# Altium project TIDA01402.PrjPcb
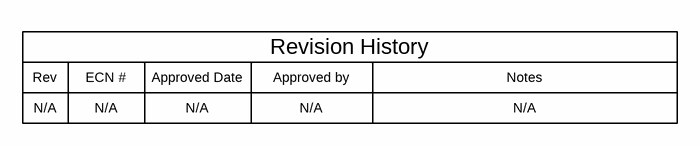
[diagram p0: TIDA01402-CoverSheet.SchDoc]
CopyrightYear: 2017; PCB_Layout: Errol Leon; PCB_Rev: E1; PRJ_Customer: Public Release; PRJ_Engineer: Errol Leon; PRJ_Number: TIDA01042; PRJ_Title: Minimizing DAC INL with zero-crossover op amp; SCH_Rev: E1; TechSupport: http://www.ti.com/support; TID: TIDA01042
3 sheets, 50 parts. Net scope: global (net labels, ports and power ports of the same name join across sheets).
Board file: TIDA01402.PcbDoc
Sheets:
  TIDA01402-CoverSheet.SchDoc
  TIDA01402-Schematic.SchDoc
  TIDA01402-Hardware.SchDoc

## Sheet TIDA01402-CoverSheet.SchDoc
size 431 x 279 mm; Date: Not shown in title block; ApprovedBy: Not shown in title block; CheckedBy: Not shown in title block; Author: Not shown in title block; CompanyName: Not shown in title block; Engineer: Not shown in title block; Organization: Not shown in title block; Address1: Not shown in title block; Address2: Not shown in title block; Address3: Not shown in title block; Address4: Not shown in title block; DocumentNumber: 1; Revision: Use project parameter SCH_Rev; SheetNumber: 1; SheetTotal: 3; PageSetup: Record=PageOptions¦CenterHorizontal=True¦CenterVertical=True¦PrintScale=1.00¦XCorrection=1.00¦YCorrection=1.00¦PrintKind=0¦BorderSize=5000000¦LeftOffset=0¦BottomOffset=0¦Orientation=2¦PaperLength=1000¦PaperWidth=1000¦Scale=100¦PaperSource=15¦PrintQuality=600¦MediaType=1¦DitherType=10¦PaperKind=Letter¦PrintScaleMode=1

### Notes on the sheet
- Rev
- N/A
- ECN #
- Approved Date
- Approved by
- Revision History
- Notes

## Sheet TIDA01402-Schematic.SchDoc
size 431 x 279 mm; Date: Not shown in title block; ApprovedBy: Not shown in title block; CheckedBy: Not shown in title block; Author: Not shown in title block; CompanyName: Not shown in title block; Engineer: Not shown in title block; Organization: Not shown in title block; Address1: Not shown in title block; Address2: Not shown in title block; Address3: Not shown in title block; Address4: Not shown in title block; DocumentNumber: 1; Revision: Use project parameter SCH_Rev; SheetNumber: 2; SheetTotal: 3; PageSetup: Record=PageOptions¦CenterHorizontal=True¦CenterVertical=True¦PrintScale=1.00¦XCorrection=1.00¦YCorrection=1.00¦PrintKind=0¦BorderSize=5000000¦LeftOffset=0¦BottomOffset=0¦Orientation=2¦PaperLength=1000¦PaperWidth=1000¦Scale=100¦PaperSource=15¦PrintQuality=-3¦MediaType=1¦DitherType=10¦PrintScaleMode=1¦PaperKind=Letter
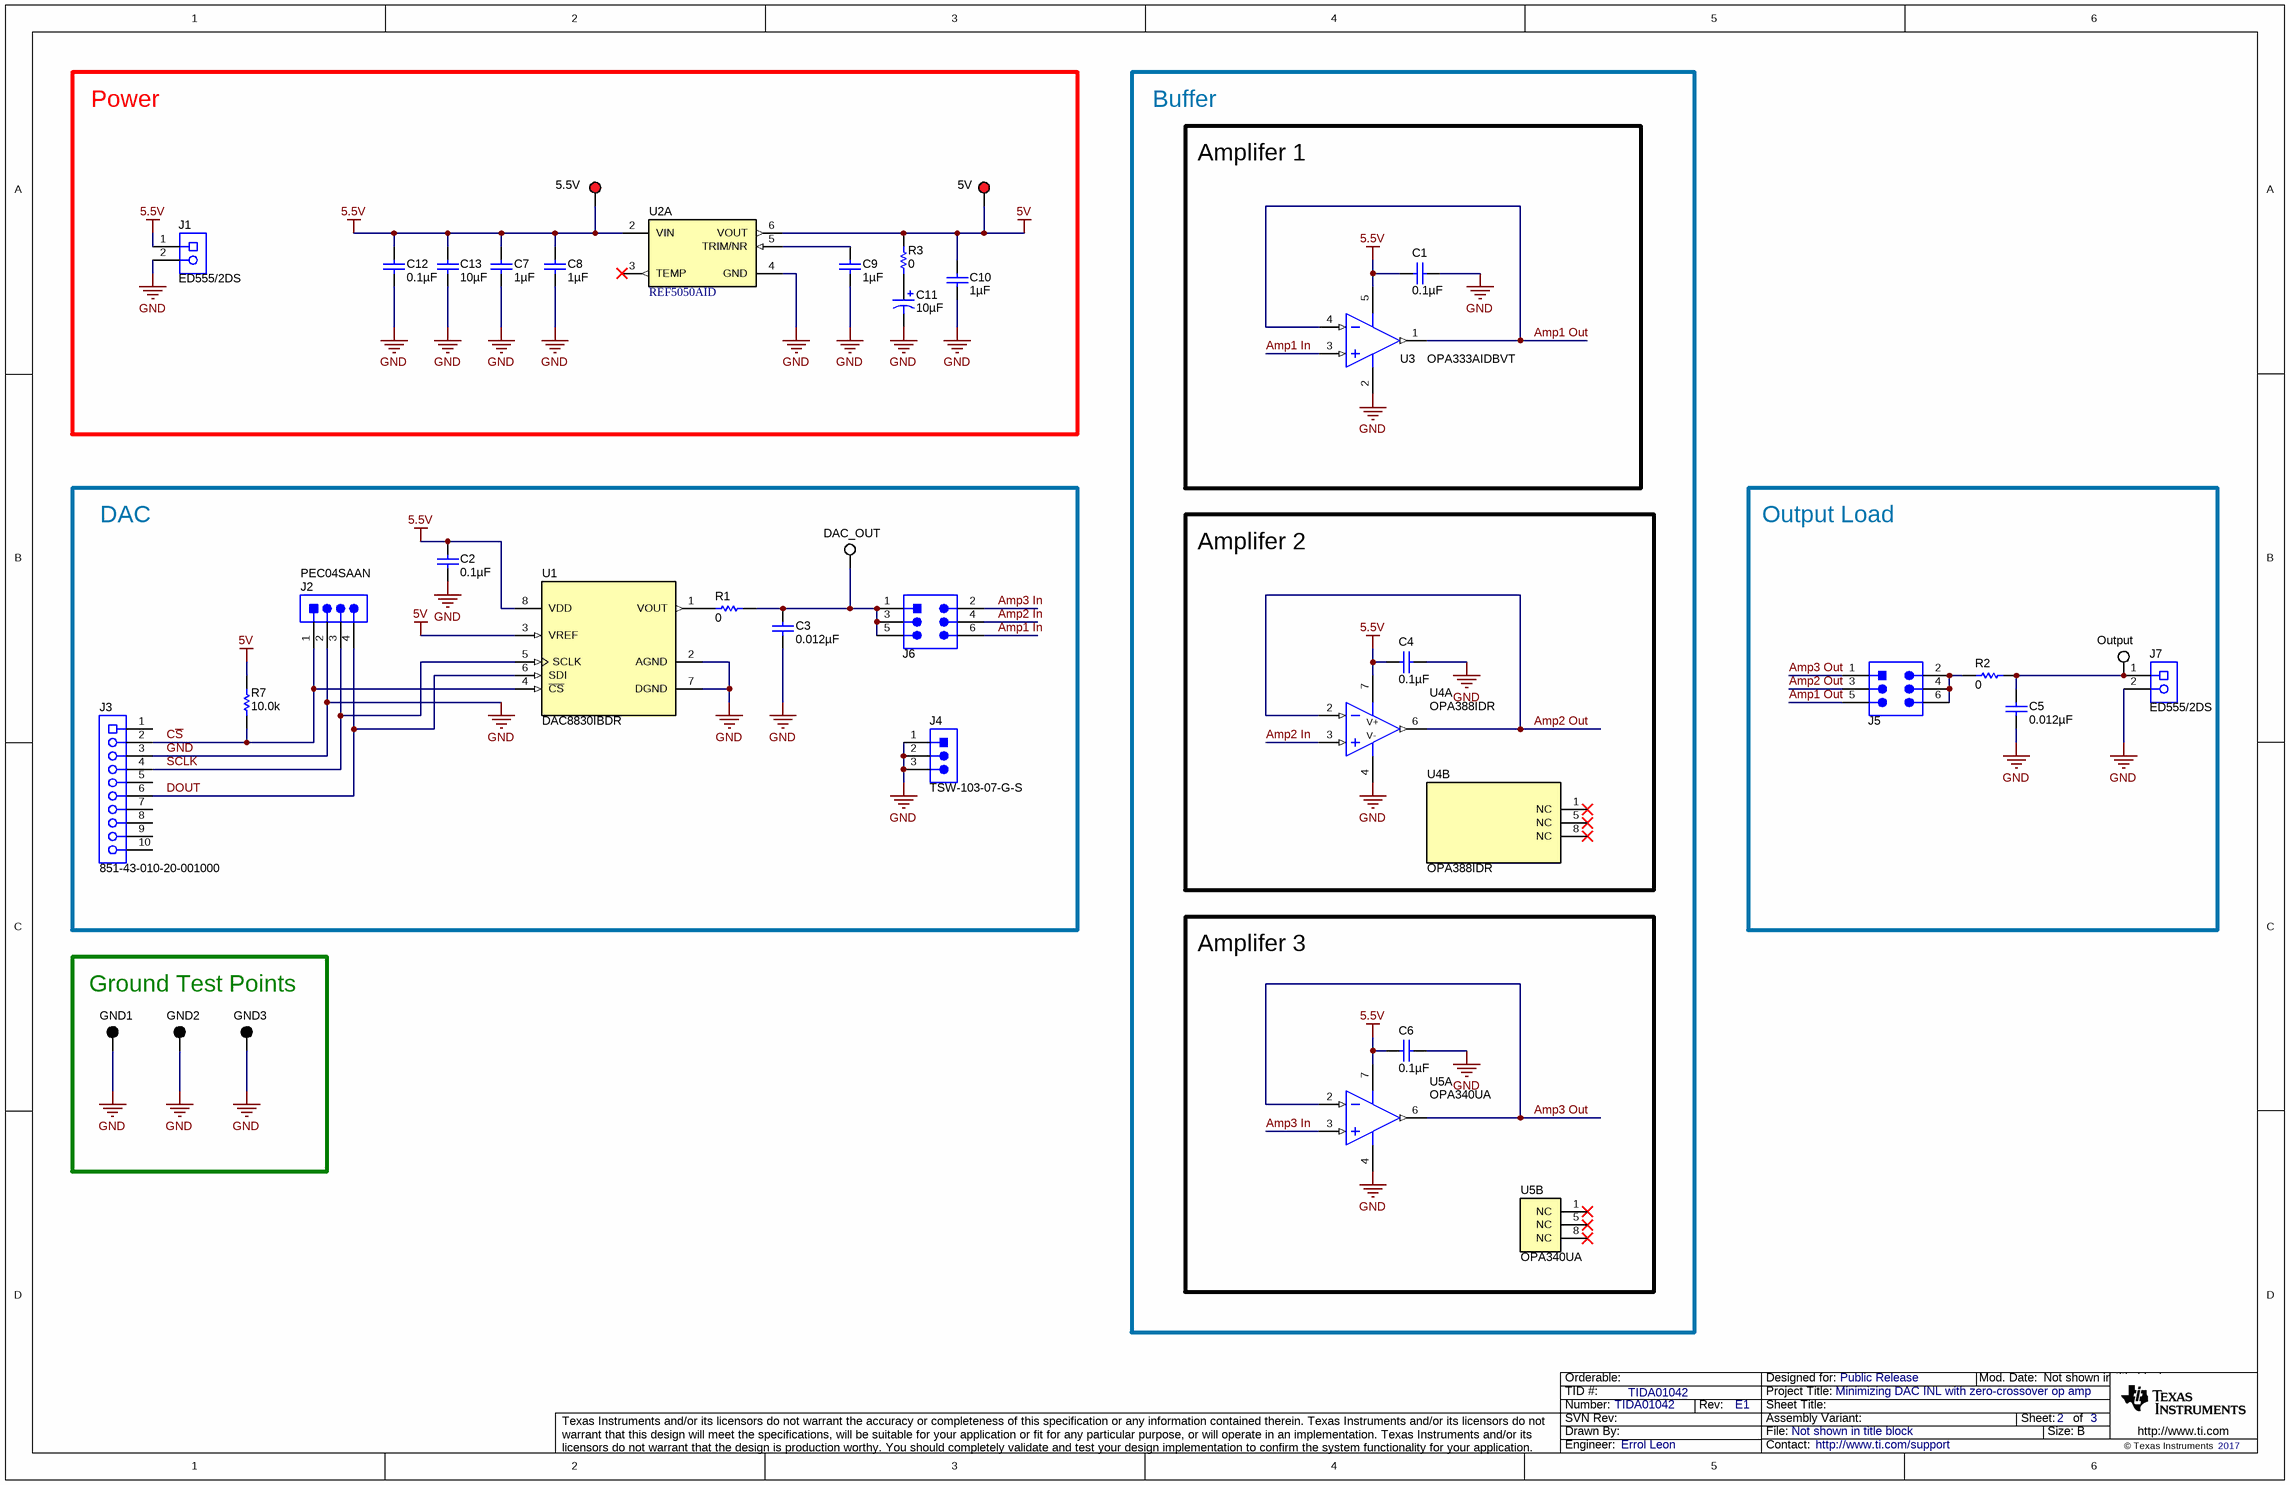
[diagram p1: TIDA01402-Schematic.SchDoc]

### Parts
5.5V  5000  [Keystone5000]  (value not drawn)
5V  5000  [Keystone5000]  (value not drawn)
C1  ValueDisplayed: 0.1µF  [0603]  (hidden comment: 06033D104KAT2A)
C2  ValueDisplayed: 0.1µF  [0603]  (hidden comment: 06033D104KAT2A)
C3  ValueDisplayed: 0.012µF  [0603]  (hidden comment: GRM188R71E123KA01D)
C4  ValueDisplayed: 0.1µF  [0603]  (hidden comment: 06033D104KAT2A)
C5  ValueDisplayed: 0.012µF  [0603]  (hidden comment: GRM188R71E123KA01D)
C6  ValueDisplayed: 0.1µF  [0603]  (hidden comment: 06033D104KAT2A)
C7  ValueDisplayed: 1µF  [0603]  (hidden comment: C1608X5R1H105K080AB)
C8  ValueDisplayed: 1µF  [0603]  (hidden comment: C1608X5R1H105K080AB)
C9  ValueDisplayed: 1µF  [0603]  (hidden comment: C1608X5R1H105K080AB)
C10  ValueDisplayed: 1µF  [0603]  (hidden comment: C1608X5R1H105K080AB)
C11  ValueDisplayed: 10µF  [3216-18]  (hidden comment: 293D106X0010A2TE3)
C12  ValueDisplayed: 0.1µF  [0603]  (hidden comment: 06033D104KAT2A)
C13  ValueDisplayed: 10µF  [0805_HV]  (hidden comment: C2012X5R1E106K125AB)
DAC_OUT  5002  [Keystone5002]  (value not drawn)
GND1  5001  [Keystone5001]  (value not drawn)
GND2  5001  [Keystone5001]  (value not drawn)
GND3  5001  [Keystone5001]  (value not drawn)
J1  ED555/2DS  [TERM_BLK_ED555-2DS]
J2  PEC04SAAN  [SULLINS_PEC04SAAN]
J3  851-43-010-20-001000  [CONN_851-43-010-20-001000]
J4  TSW-103-07-G-S  [TSW-103-07-G-S]
J5  TSW-103-07-G-D  [TSW-103-07-G-D]  (value not drawn)
J6  TSW-103-07-G-D  [TSW-103-07-G-D]  (value not drawn)
J7  ED555/2DS  [TERM_BLK_ED555-2DS]
Output  5002  [Keystone5002]  (value not drawn)
R1  ValueDisplayed: 0  [0603]  (hidden comment: RC0603JR-070RL)
R2  ValueDisplayed: 0  [0603]  (hidden comment: RC0603JR-070RL)
R3  ValueDisplayed: 0  [0603]  (hidden comment: RC0603JR-070RL)
R7  ValueDisplayed: 10.0k  [0603]  (hidden comment: CRCW060310K0FKEA)
U1  DAC8830IBDR  [D0008A_N]
U2  REF5050AID  [D0008A_N]  (part A of 2)
U3  OPA333AIDBVT  [DBV0005A_N]
U4  OPA388IDR  [D0008A_N]  (parts A,B of 2)
U5  OPA340UA  [D0008A_N]  (parts A,B of 2)

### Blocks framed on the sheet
Power: 5.5V 5V C7-C13 J1 R3 U2
Amplifer 1: C1 U3
DAC: C2 C3 DAC_OUT J2-J4 J6 R1 R7 U1
Amplifer 2: C4 U4
Output Load: C5 J5 J7 Output R2
Ground Test Points: GND1-GND3
Amplifer 3: C6 U5

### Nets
5.5V: 5.5V.1 C1.2 C2.1 C4.2 C6.2 C7.1 C8.1 C12.1 C13.1 J1.1 U1.8(VDD) U2.2(VIN) U3.5(V+) U4.7(V+) U5.7(V+)
5V: 5V.1 C10.1 R3.2 R7.2 U1.3(VREF) U2.6(VOUT)
GND: C1.1 C2.2 C3.2 C4.1 C5.2 C6.1 C7.2 C8.2 C9.2 C10.2 C11.2(-) C12.2 C13.2 GND1.1 GND2.1 GND3.1 J1.2 J2.2 J3.3 J4.1 J4.2 J4.3 J7.2 U1.2(AGND) U1.7(DGND) U2.4(GND) U3.2(V-) U4.4(V-) U5.4(V-)
C~{S}: J2.1 J3.2 R7.1 U1.4(~{CS})
Amp1 In: J6.6 U3.3(IN+)
Amp1 Out: J5.5 U3.1(OUT) U3.4(IN-)
Amp2 In: J6.4 U4.3(IN+)
Amp2 Out: J5.3 U4.2(IN-) U4.6(OUT)
Amp3 In: J6.2 U5.3(IN+)
Amp3 Out: J5.1 U5.2(IN-) U5.6(OUT)
DOUT: J2.4 J3.6 U1.6(SDI)
SCLK: J2.3 J3.4 U1.5(SCLK)
NetC3_1: C3.1 DAC_OUT.1 J6.1 J6.3 J6.5 R1.2
NetC5_1: C5.1 J7.1 Output.1 R2.2
NetC9_1: C9.1 U2.5(TRIM/NR)
NetC11_1: C11.1(+) R3.1
NetJ5_2: J5.2 J5.4 J5.6 R2.1
NetR1_1: R1.1 U1.1(VOUT)

Not connected (* = marked no-connect by the designer): J3 1 5 7 8 9 10; U2 3(TEMP)*; U4 1(NC)* 5(NC)* 8(NC)*; U5 1(NC)* 5(NC)* 8(NC)*

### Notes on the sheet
- Buffer

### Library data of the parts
5.5V 5V = 5000: Test Point, Miniature, Red, TH; Manufacturer: Keystone; CompType: Test Point Loop; ContactFinish: Silver
C1 C2 C4 C6 C12 = 06033D104KAT2A: CAP, CERM, 0.1 µF, 25 V, +/- 10%, X5R, 0603; Manufacturer: AVX; Polarized: N; CompType: Capacitor; Value: 0.1uF; U/M: EA; Cap_F: 0.0000001; Tolerance_%: 10; ESR_ohm: 0.048; Value1: 0.048 ohm; VDC_V: 25; Value2: 25V; IRMS_A: 0.53; TaMin_C: -55; TaMax_C: 85; SizeArea_mm2: 1.28; SizeAreaWB_mm2: 4.68; SizeX_mm: 1.6; SizeY_mm: 0.8; SizeZ_mm: 1; AEC Category: Q200
C3 C5 = GRM188R71E123KA01D: CAP, CERM, 0.012 µF, 25 V, +/- 10%, X7R, 0603; Manufacturer: MuRata; Polarized: N; CompType: Capacitor; Value: 0.012uF; U/M: EA; Cap_F: 0.000000012; Tolerance_%: 10; Value1: Unknown; VDC_V: 25; Value2: 25V; TaMin_C: -55; TaMax_C: 125; SizeArea_mm2: 1.28; SizeAreaWB_mm2: 4.68; SizeX_mm: 1.6; SizeY_mm: 0.8; SizeZ_mm: 1; AEC Category: Q200
C7-C10 = C1608X5R1H105K080AB: CAP, CERM, 1 µF, 50 V, +/- 10%, X5R, 0603; Manufacturer: TDK; Polarized: N; CompType: Capacitor; Value: 1uF; U/M: EA; Cap_F: 0.000001; Tolerance_%: 10; ESR_ohm: 0.005522; Value1: 0.005522 ohm; VDC_V: 50; Value2: 50V; IRMS_A: 2.21617; TaMin_C: -55; TaMax_C: 85; SizeArea_mm2: 1.28; SizeAreaWB_mm2: 4.68; SizeX_mm: 1.6; SizeY_mm: 0.8; SizeZ_mm: 1; AEC Category: Q200
C11 = 293D106X0010A2TE3: CAP, TA, 10 µF, 10 V, +/- 20%, 3.4 ohm, SMD; Manufacturer: Vishay-Sprague; Polarized: Y; CompType: Capacitor; Value: 10uF; U/M: EA; Cap_F: 0.00001; Tolerance_%: 20; Value1: 3.4 ohm; VDC_V: 10; Value2: 10V; ESR_ohm: 3.4; IRMS_A: 0.15; TaMin_C: -55; TaMax_C: 125; Cap_Case: A; SizeAreaWB_mm2: 10.92; SizeArea_mm2: 5.12; SizeX_mm: 3.2; SizeY_mm: 1.6; SizeZ_mm: 1.8; AEC Category: Q200
C13 = C2012X5R1E106K125AB: CAP, CERM, 10 µF, 25 V, +/- 10%, X5R, 0805; Manufacturer: TDK; Polarized: N; CompType: Capacitor; Value: 10uF; U/M: EA; Cap_F: 0.00001; Tolerance_%: 10; Value1: Unknown; VDC_V: 25; Value2: 25V; TaMin_C: -55; TaMax_C: 85; Cap_Case: 0805; SizeArea_mm2: 2.5; SizeAreaWB_mm2: 6.75; SizeX_mm: 2; SizeY_mm: 1.25; SizeZ_mm: 1.45; AEC Category: Q200
DAC_OUT Output = 5002: Test Point, Miniature, White, TH; Manufacturer: Keystone; CompType: Test Point Loop; ContactFinish: Silver
GND1-GND3 = 5001: Test Point, Miniature, Black, TH; Manufacturer: Keystone; CompType: Test Point Loop; ContactFinish: Silver
J1 J7 = ED555/2DS: Terminal Block, 3.5mm Pitch, 2x1, TH; Manufacturer: On-Shore Technology; SymbolCreator: a0412235; Pitch_mm: 3.5; Gender: Female; Shrouded: N; Row_Count: 1; ContactFinish: Brass; Current_A: 6; Voltage_V: 150; Cert_CULUS: Y
J2 = PEC04SAAN: Header, 100mil, 4x1, Tin, TH; Manufacturer: Sullins Connector Solutions; SymbolCreator: a0412235; Pitch_mm: 2.54; Gender: Male; Shrouded: N; Row_Count: 1; Current_A: 3; Voltage_V: 1800; Cert_UL: Y
J3 = 851-43-010-20-001000: Receptacle, 50mil, 10x1, Gold, R/A, TH; Manufacturer: Mill-Max; SymbolCreator: a0411947
J4 = TSW-103-07-G-S: Header, 100mil, 3x1, Gold, TH; Manufacturer: Samtec; SymbolCreator: a0799628; Pitch_mm: 2.54; Gender: Male; Shrouded: N; Row_Count: 1; Current_A: 6.3; Voltage_V: 550; Cert_CSA: Y
J5 J6 = TSW-103-07-G-D: Header, 100mil, 3x2, Gold, TH; Manufacturer: Samtec; SymbolCreator: a0412235; Pitch_mm: 2.54; Gender: Male; Shrouded: N; Row_Count: 2; Current_A: 6.3; Voltage_V: 550; Cert_CSA: Y
R1-R3 = RC0603JR-070RL: RES, 0, 5%, 0.1 W, 0603; Manufacturer: Yageo America; CompType: Resistor; Value: 0; Value_Code: 0000; Tolerance_%: 5; Power_W: 0.1; Value2: 0.1W; VDC_V: 50; TempCo: 200 ppm/C; SizeArea_mm2: 1.28; SizeX_mm: 1.6; SizeY_mm: 0.8; SizeZ_mm: 1; EIA_Code: E24; U/M: EA; AEC Category: Q200
R7 = CRCW060310K0FKEA: RES, 10.0 k, 1%, 0.1 W, 0603; Manufacturer: Vishay-Dale; CompType: Resistor; Value: 10.0k; Res_ohm: 10000; Value_Code: 10k0; Tolerance_%: 1; Power_W: 0.1; Value2: 0.1W; VDC_V: 75; TempCo: 100 ppm/C; SizeArea_mm2: 1.28; SizeX_mm: 1.6; SizeY_mm: 0.8; EIA_Code: E96; U/M: EA; AEC Category: Q200
U1 = DAC8830IBDR: 16-Bit, Ultra-Low Power, Voltage-Output Digital-to-Analog Converter, D0008A (SOIC-8); Manufacturer: Texas Instruments; SymbolCreator: Altium; SizeArea_mm2: 30.38; SizeAreaWB_mm2: 56.58; SizeX_mm: 4.9; SizeY_mm: 6.2; SizeZ_mm: 1.75; CompType: IC; U/M: EA
U2 = REF5050AID: Low Noise, Very Low Drift, Precision Voltage Reference, -40 to 125 degC, 8-pin SOIC (D), Green (RoHS & no Sb/Br); Manufacturer: Texas Instruments; Alternate PartNumber: Equivalent; Initial Accuracy @ 25/deg C(%): 0.05; Iout/Iz(Max)(mA): 10; Iq(Max)(uA): 1000; Rating: Catalog; SubFamily: Series Voltage Reference; Temp Coeff(Max)(ppm/ degree C): 3; VI(Max)(V): 18; VI(Min)(V): 5.2; VO(V): 5
U3 = OPA333AIDBVT: 17 uA, MicroPower, Precision, Zero Drift CMOS Operational Amplifier, 1.8 to 5.5 V, -40 to 125 degC, 5-pin SOT23 (DBV0005A), Green (RoHS & no Sb/Br); Manufacturer: Texas Instruments; Alternate PartNumber: Equivalent; CMRR(Min)(dB): 106; IIB(Max)(pA): 200; Iq per channel(Max)(mA): 0.025; Number of Channels: 1; Offset Drift(Typ)(uV/C): 0.02; Slew Rate(Typ)(V/us): 0.16; Sub Family: Low Offset Voltage Amplifier (<=500uV), Low Power Amp (<=500uA), Low Supply Voltage Amplifier (<=2.7V), Precision Amplifier, Zero Drift Precision Amplifier; Total Supply Voltage(Max)(+5V is 5, +/-5V is 10): 5.5; Total Supply Voltage(Min)(+5V is 5, +/-5V is 10): 1.8; Vio (25C)(Max)(mV): 0.01
U4 = OPA388IDR: Precision, Zero-Drift, Zero-Crossover, True Rail-to-Rail Input/Output, Operational Amplifier, D0008A (SOIC-8); Manufacturer: Texas Instruments; SymbolCreator: a0411595/a0412235; SizeArea_mm2: 30.38; SizeAreaWB_mm2: 56.58; SizeX_mm: 4.9; SizeY_mm: 6.2; SizeZ_mm: 1.75; CompType: IC; U/M: EA
U5 = OPA340UA: Single-Supply, Rail-to-Rail Operational Amplifier MicroAmplifier(TM) Series, 2.7 to 5.5 V, -40 to 85 degC, 8-pin SOIC (D0008A), Green (RoHS & no Sb/Br); Manufacturer: Texas Instruments; Alternate PartNumber: Equivalent; CMRR(Min)(dB): 80; IIB(Max)(pA): 10; Iq per channel(Max)(mA): 0.95; Number of Channels: 1; Offset Drift(Typ)(uV/C): 2.5; Slew Rate(Typ)(V/us): 6; Sub Family: Low Input Bias Current Amp (<=10pA), Low Offset Voltage Amplifier (<=500uV), Low Supply Voltage Amplifier (<=2.7V), Precision Amplifier; Total Supply Voltage(Max)(+5V is 5, +/-5V is 10): 5.5; Total Supply Voltage(Min)(+5V is 5, +/-5V is 10): 2.7; Vio (25C)(Max)(mV): 0.5; Vn at 1kHz(Typ)(nV/rtHz): 25

## Sheet TIDA01402-Hardware.SchDoc
size 431 x 279 mm; Date: Not shown in title block; ApprovedBy: Not shown in title block; CheckedBy: Not shown in title block; Author: Not shown in title block; CompanyName: Not shown in title block; Engineer: Not shown in title block; Organization: Not shown in title block; Address1: Not shown in title block; Address2: Not shown in title block; Address3: Not shown in title block; Address4: Not shown in title block; DocumentNumber: 1; Revision: Use project parameter SCH_Rev; SheetNumber: 3; SheetTotal: 3; PageSetup: Record=PageOptions¦CenterHorizontal=True¦CenterVertical=True¦PrintScale=1.00¦XCorrection=1.00¦YCorrection=1.00¦PrintKind=0¦BorderSize=5000000¦LeftOffset=0¦BottomOffset=0¦Orientation=2¦PaperLength=1000¦PaperWidth=1000¦Scale=100¦PaperSource=15¦PrintQuality=600¦MediaType=1¦DitherType=10¦PaperKind=Letter¦PrintScaleMode=1
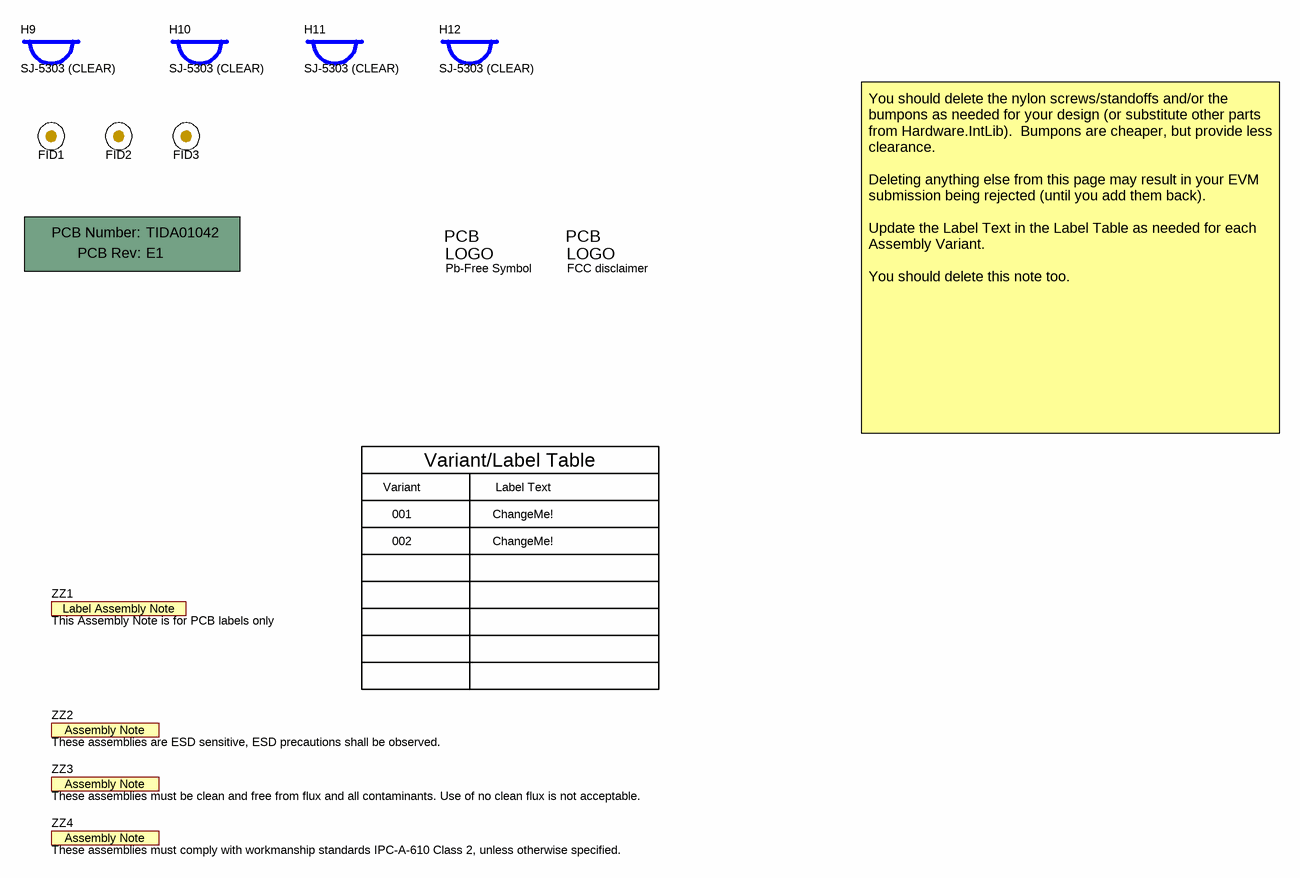
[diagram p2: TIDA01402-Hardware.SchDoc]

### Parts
!PCB1  Printed Circuit Board  (value not drawn)  (mechanical)
FID1  Fiducial  [Fiducial10-20]  (value not drawn)
FID2  Fiducial  [Fiducial10-20]  (value not drawn)
FID3  Fiducial  [Fiducial10-20]  (value not drawn)
H9  SJ-5303 (CLEAR)  [Bumpon_SJ5003Transparent]
H10  SJ-5303 (CLEAR)  [Bumpon_SJ5003Transparent]
H11  SJ-5303 (CLEAR)  [Bumpon_SJ5003Transparent]
H12  SJ-5303 (CLEAR)  [Bumpon_SJ5003Transparent]
Logo2  Pb-Free Symbol  [Pb-Free_Overlay_Small]  (no BOM)
Logo3  FCC disclaimer  [FCC_disclaimer]  (no BOM)
ZZ1  This Assembly Note is for PCB labels only  [AssemblyNoteLabel]  (no BOM)
ZZ2  These assemblies are ESD sensitive, ESD precautions shall be observed.  [AssemblyNote]  (no BOM)
ZZ3  These assemblies must be clean and free from flux and all contaminants. Use of no clean flux is not acceptable.  [AssemblyNote]  (no BOM)
ZZ4  These assemblies must comply with workmanship standards IPC-A-610 Class 2, unless otherwise specified.  [AssemblyNote]  (no BOM)

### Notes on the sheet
- Variant
- Variant/Label Table
- Label Text
- You should delete the nylon screws/standoffs and/or the bumpons as needed for your design (or substitute other parts from Hardware.IntLib).  Bumpons are cheaper, but provide less clearance.
  Deleting anything else from this page may result in your EVM submission being rejected (until you add them back).
  Update the Label Text in the Label Table as needed for each Assembly Variant.
  You should delete this note too.
- 001
- 002
- ChangeMe!

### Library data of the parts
!PCB1 = PCB: Manufacturer: Any; PartNumber: TIDA01042; SymbolCreator: a0412235
FID1-FID3 = Fiducial: Fiducial mark.  There is nothing to buy or mount.; SymbolCreator: codlsc
H9-H12 = SJ-5303 (CLEAR): Bumpon, Hemisphere, 0.44 X 0.20, Clear; Manufacturer: 3M; SymbolCreator: a0412235
Logo2 = Pb-Free: SymbolCreator: a0412235
Logo3 = FCC_disclaimer: SymbolCreator: codlsc
ZZ1 = AssemblyNoteLabel: SymbolCreator: a0412235
ZZ2-ZZ4 = AssemblyNote: SymbolCreator: codlsc

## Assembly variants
001: not fitted C1 C3 C5 C7 U3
